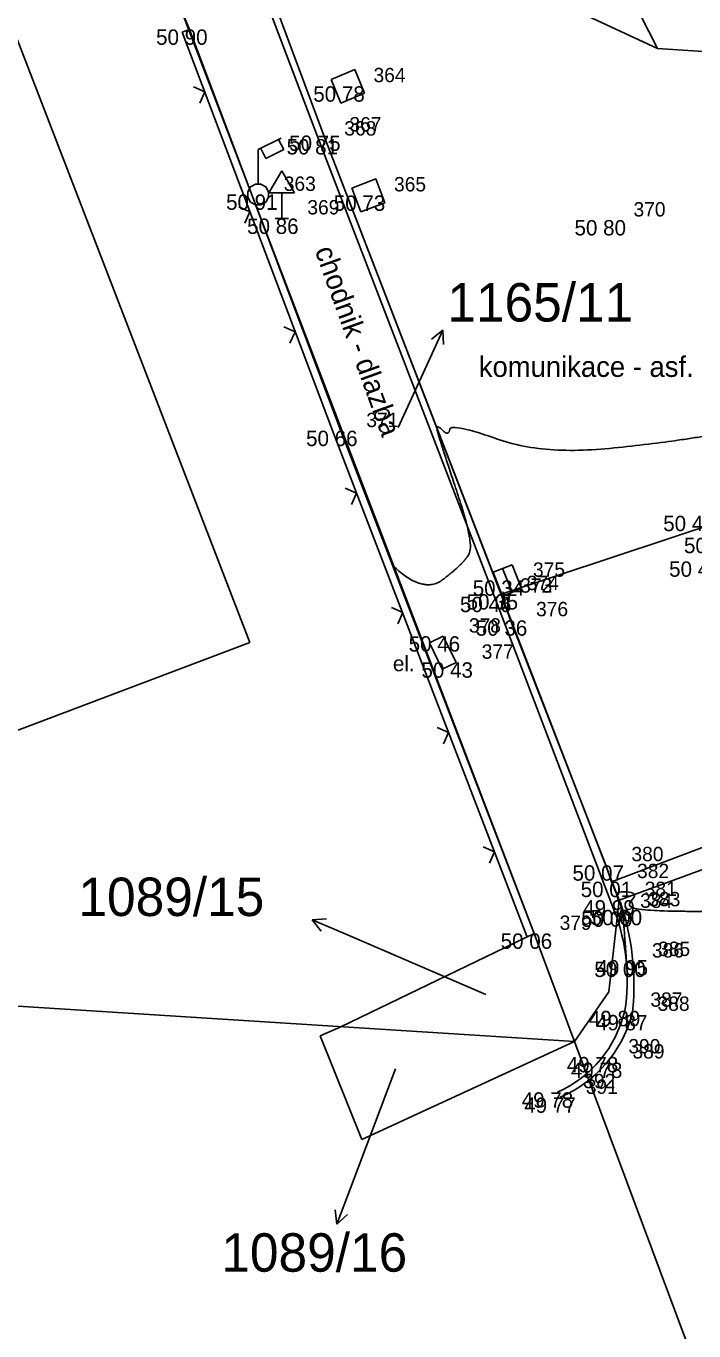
# Model space of a CAD drawing. Extents: x -704057 to -703795, y -1008732 to -1008584.
# Drawn here: x -703998.45 to -703985.42, y -1008681.82 to -1008656.35 of the extents above; entities that cross this region are included whole.
import ezdxf

# ---------------------------------------------------------------- set-up
doc = ezdxf.new("R2010")
doc.units = 0
for name, color, linetype in [('Z_body', 7, 'Continuous'), ('Z_body_cisla', 7, 'Continuous'), ('Z_body_vysky', 7, 'Continuous'), ('Z_dopravni_znaceni', 7, 'Continuous'), ('Z_katastr_cisla_pozemkove', 7, 'Continuous'), ('Z_katastr_hranice', 7, 'Continuous'), ('Z_komunikace_zpevn_pl', 7, 'Continuous'), ('Z_obruby', 7, 'Continuous'), ('Z_oploceni', 7, 'Continuous'), ('Z_popis', 7, 'Continuous'), ('Z_rozhrani_zpevn', 7, 'Continuous'), ('Z_site_pilire', 7, 'Continuous'), ('Z_site_znaky_kanalizace', 7, 'Continuous'), ('Z_site_znaky_VO', 7, 'Continuous'), ('Z_site_znaky_vodovod', 7, 'Continuous'), ('Z_vrstevnice_hlavni', 7, 'Continuous'), ('Z_vrstevnice_vedlejsi', 7, 'Continuous'), ('Z_vstupy', 7, 'Continuous')]:
    doc.layers.add(name, color=color, linetype=linetype)

# ---------------------------------------------------------------- blocks, each defined once
blk = doc.blocks.new('POINT_DISPLAY')
blk.add_line((0, 0), (0, 0))
blk = doc.blocks.new('Z212')
for p, q in [((-0.17, 0.17), (0, 0)), ((0, 0), (0.17, 0.17))]:
    blk.add_line(p, q)
blk = doc.blocks.new('Z13')
for p, q in [((0, 0.88), (0.45, 1.1)), ((0.4, 1.07), (0.5, 0.88)), ((0, 0.2), (0, 0.88)), ((0.15, 0.7), (0.05, 0.9)), ((0.5, 0.88), (0.15, 0.7)), ((-0.2, 0.05), (-0.15, 0.15)), ((-0.2, -0.05), (-0.2, 0.05)), ((-0.15, 0.15), (-0.05, 0.2)), ((-0.05, 0.2), (0.05, 0.2)), ((0.05, 0.2), (0.15, 0.15)), ((0.15, 0.15), (0.2, 0.05)), ((0.2, 0.05), (0.2, -0.05)), ((-0.15, -0.15), (-0.2, -0.05)), ((-0.05, -0.2), (-0.15, -0.15)), ((0.05, -0.2), (-0.05, -0.2)), ((0.15, -0.15), (0.05, -0.2)), ((0.2, -0.05), (0.15, -0.15))]:
    blk.add_line(p, q)
blk = doc.blocks.new('Z38')
for p, q in [((0.25, 0.2), (-0.25, 0.2)), ((-0.25, 0.2), (-0.25, -0.2)), ((-0.25, 0), (0.25, 0)), ((0.25, -0.2), (0.25, 0.2)), ((-0.25, -0.2), (0.25, -0.2))]:
    blk.add_line(p, q)
blk = doc.blocks.new('Z608')
for p, q in [((0.25, 0.25), (-0.25, 0.25)), ((-0.25, 0.25), (-0.25, -0.25)), ((0.25, -0.25), (0.25, 0.25)), ((-0.25, -0.25), (0.25, -0.25))]:
    blk.add_line(p, q)
blk = doc.blocks.new('Z527')
for p, q in [((0, 0.93), (-0.25, 0.5)), ((0.25, 0.5), (0, 0.93)), ((-0.25, 0.5), (0.25, 0.5)), ((0, 0), (0, 0.5)), ((-0.13, 0), (0.13, 0))]:
    blk.add_line(p, q)
blk = doc.blocks.new('Z61')
for p, q in [((0, 0.75), (-0.13, 0.5)), ((0, 0), (0, 0.75)), ((0, 0.75), (0.13, 0.5))]:
    blk.add_line(p, q)

msp = doc.modelspace()

# ---------------------------------------------------------------- linework, layer by layer
at = {"layer": 'Z_katastr_cisla_pozemkove'}
for points in [[(-703991.19, -1008664.19), (-703990.63, -1008662.97)], [(-703989.48, -1008675.25), (-703992.18, -1008674.09)], [(-703991.24, -1008676.7), (-703992.12, -1008679.03)]]:
    msp.add_lwpolyline(points, dxfattribs=at)
at = {"layer": 'Z_katastr_hranice'}
for p, q in [((-703986.13, -1008656.79), (-703989.65, -1008649.86)), ((-703986.13, -1008656.79), (-703996.49, -1008651.97)), ((-703992.64, -1008658.49), (-703994.45, -1008653.63)), ((-703996.14, -1008654.16), (-703988.54, -1008674.06)), ((-703994.08, -1008668.38), (-703999.05, -1008655.49)), ((-703977.9, -1008657.35), (-703986.13, -1008656.79)), ((-703986.88, -1008673.41), (-703992.64, -1008658.49)), ((-703994.08, -1008668.38), (-704002.01, -1008671.38)), ((-703987.08, -1008675.2), (-703986.88, -1008673.41)), ((-703987.75, -1008676.17), (-704026.16, -1008673.72)), ((-703988.54, -1008674.06), (-703992.31, -1008675.88)), ((-703982, -1008691.57), (-703988.54, -1008674.06)), ((-703987.75, -1008676.17), (-703987.08, -1008675.2)), ((-703992.31, -1008675.88), (-703992.71, -1008676.06)), ((-703992.71, -1008676.06), (-703991.9, -1008678.08)), ((-703991.9, -1008678.08), (-703987.75, -1008676.17))]:
    msp.add_line(p, q, dxfattribs=at)
at = {"layer": 'Z_komunikace_zpevn_pl'}
for p, q in [((-703994.45, -1008653.63), (-703992.64, -1008658.49)), ((-703992.64, -1008658.49), (-703989.18, -1008667.44)), ((-703989.18, -1008667.44), (-703989, -1008667.95)), ((-703989, -1008667.95), (-703987.14, -1008672.73)), ((-703987.14, -1008672.73), (-703987.03, -1008673.05)), ((-703987.03, -1008673.05), (-703986.88, -1008673.41)), ((-703986.88, -1008673.41), (-703986.81, -1008673.6))]:
    msp.add_line(p, q, dxfattribs=at)
for centre, radius, start, end in [((-703991.75, -1008675.07), 5.158, 353.5102, 16.5257), ((-703989.02, -1008674.98), 2.483, 293.5439, 344.438)]:
    msp.add_arc(centre, radius, start, end, dxfattribs=at)
at = {"layer": 'Z_obruby'}
for p, q in [((-703992.74, -1008658.56), (-703994.6, -1008653.67)), ((-703992.74, -1008658.56), (-703989.31, -1008667.49)), ((-703989.31, -1008667.49), (-703986.97, -1008673.63))]:
    msp.add_line(p, q, dxfattribs=at)
for centre, radius, start, end in [((-703990.49, -1008674.97), 3.768, 350.8881, 20.8839), ((-703989.03, -1008675.04), 2.32, 294.152, 346.8779)]:
    msp.add_arc(centre, radius, start, end, dxfattribs=at)
at = {"layer": 'Z_oploceni'}
for p, q in [((-703995.4, -1008656.47), (-703995.26, -1008656.42)), ((-703995.26, -1008656.42), (-703992.31, -1008664.25)), ((-703995.4, -1008656.47), (-703992.45, -1008664.3)), ((-703992.45, -1008664.3), (-703988.68, -1008674.11)), ((-703992.31, -1008664.25), (-703988.54, -1008674.06))]:
    msp.add_line(p, q, dxfattribs=at)
at = {"layer": 'Z_rozhrani_zpevn'}
for p, q in [((-703989.18, -1008667.44), (-703981.87, -1008665.01)), ((-703987.03, -1008673.05), (-703979.93, -1008670.37)), ((-703986.88, -1008673.41), (-703983.37, -1008672.12))]:
    msp.add_line(p, q, dxfattribs=at)
at = {"layer": 'Z_site_pilire'}
for p, q in [((-703990.58, -1008668.39), (-703990.31, -1008668.26)), ((-703990.33, -1008668.9), (-703990.58, -1008668.39)), ((-703990.06, -1008668.77), (-703990.31, -1008668.26)), ((-703990.33, -1008668.9), (-703990.06, -1008668.77))]:
    msp.add_line(p, q, dxfattribs=at)
at = {"layer": 'Z_vrstevnice_hlavni'}
msp.add_open_spline([(-703986.743, -1008674.608), (-703986.74, -1008674.61), (-703986.737, -1008674.589), (-703986.81, -1008673.6), (-703986.889, -1008673.432), (-703986.955, -1008673.23), (-703986.49, -1008673.267), (-703986.81, -1008673.6), (-703985.37, -1008673.634), (-703985.333, -1008673.63), (-703981.787, -1008673.594), (-703980.2, -1008672.735), (-703978.988, -1008673.004), (-703978.692, -1008673.627), (-703978.153, -1008674.88), (-703977.349, -1008675.544), (-703975.53, -1008676.91)], degree=2, dxfattribs=at)
at = {"layer": 'Z_vrstevnice_vedlejsi'}
msp.add_open_spline([(-703991.305, -1008666.866), (-703990.71, -1008667.458), (-703989.91, -1008666.842), (-703989.702, -1008666.469), (-703990.341, -1008664.544), (-703990.478, -1008664.084), (-703990.202, -1008664.369), (-703990.172, -1008664.089), (-703988.378, -1008664.725), (-703985.803, -1008664.468), (-703984.247, -1008664.174), (-703982.363, -1008663.613), (-703981.838, -1008664.665), (-703981.808, -1008664.722), (-703981.703, -1008664.79), (-703979.237, -1008666.262), (-703979.164, -1008666.207), (-703978.967, -1008666.455), (-703978.04, -1008666.762), (-703976.651, -1008665.634)], degree=2, dxfattribs=at)
at = {"layer": 'Z_vstupy'}
msp.add_line((-703995.66, -1008655.45), (-703995.26, -1008656.42), dxfattribs=at)

# ---------------------------------------------------------------- block references
at = {"layer": 'Z_body'}
for p in [(-703995.26, -1008656.42), (-703992.17, -1008657.53), (-703992.74, -1008658.56), (-703992.64, -1008658.49), (-703993.92, -1008659.64), (-703991.77, -1008659.66), (-703993.46, -1008660.11), (-703987.1, -1008660.14), (-703992.31, -1008664.25), (-703989.06, -1008667.17), (-703989.31, -1008667.49), (-703989.31, -1008667.49), (-703989.18, -1008667.44), (-703989, -1008667.95), (-703990.31, -1008668.26), (-703990.06, -1008668.77), (-703987.14, -1008672.73), (-703987.03, -1008673.05), (-703986.88, -1008673.41), (-703986.97, -1008673.63), (-703986.81, -1008673.6), (-703988.54, -1008674.06), (-703986.74, -1008674.61), (-703986.62, -1008674.58), (-703986.77, -1008675.57), (-703986.63, -1008675.65), (-703987.2, -1008676.47), (-703987.12, -1008676.58), (-703988.08, -1008677.16), (-703988.03, -1008677.26)]:
    msp.add_blockref('POINT_DISPLAY', p, dxfattribs=at)
at = {"layer": 'Z_dopravni_znaceni'}
msp.add_blockref('Z527', (-703993.46, -1008660.11), dxfattribs=at)
at = {"layer": 'Z_katastr_cisla_pozemkove'}
for p, rotation in [((-703990.63, -1008662.97), -24.775100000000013), ((-703992.18, -1008674.09), 66.8014), ((-703992.12, -1008679.03), 159.1932)]:
    msp.add_blockref('Z61', p, dxfattribs=dict(at, rotation=rotation))
at = {"layer": 'Z_oploceni'}
for p, rotation in [((-703994.96, -1008657.64), 110.60000000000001), ((-703994.08, -1008659.98), 110.60000000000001), ((-703993.2, -1008662.32), 110.60000000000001), ((-703992, -1008665.47), 111), ((-703991.1, -1008667.8), 111), ((-703990.21, -1008670.14), 111), ((-703989.31, -1008672.47), 111)]:
    msp.add_blockref('Z212', p, dxfattribs=dict(at, rotation=rotation))
at = {"layer": 'Z_site_znaky_kanalizace', "rotation": -68.39999999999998}
msp.add_blockref('Z38', (-703989.06, -1008667.17), dxfattribs=at)
at = {"layer": 'Z_site_znaky_VO'}
msp.add_blockref('Z13', (-703993.92, -1008659.64), dxfattribs=at)
at = {"layer": 'Z_site_znaky_vodovod'}
for p, rotation in [((-703992.17, -1008657.53), 22.500000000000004), ((-703991.77, -1008659.66), 20.7)]:
    msp.add_blockref('Z608', p, dxfattribs=dict(at, rotation=rotation))

# ---------------------------------------------------------------- texts
at = {"layer": 'Z_body_cisla'}
for s, p in [('364', (-703991.67, -1008657.45)), ('368', (-703992.24, -1008658.49)), ('367', (-703992.14, -1008658.41)), ('363', (-703993.42, -1008659.57)), ('365', (-703991.27, -1008659.58)), ('369', (-703992.96, -1008660.03)), ('370', (-703986.6, -1008660.07)), ('371', (-703991.81, -1008664.18)), ('375', (-703988.56, -1008667.1)), ('372', (-703988.81, -1008667.41)), ('373', (-703988.81, -1008667.41)), ('374', (-703988.68, -1008667.36)), ('376', (-703988.5, -1008667.87)), ('378', (-703989.81, -1008668.19)), ('377', (-703989.56, -1008668.7)), ('380', (-703986.64, -1008672.65)), ('382', (-703986.53, -1008672.98)), ('381', (-703986.38, -1008673.33)), ('384', (-703986.47, -1008673.56)), ('383', (-703986.31, -1008673.53)), ('379', (-703988.04, -1008673.99)), ('386', (-703986.24, -1008674.53)), ('385', (-703986.12, -1008674.5)), ('387', (-703986.27, -1008675.49)), ('388', (-703986.13, -1008675.57)), ('390', (-703986.7, -1008676.4)), ('389', (-703986.62, -1008676.5)), ('392', (-703987.58, -1008677.08)), ('391', (-703987.53, -1008677.19))]:
    msp.add_text(s, height=0.28, dxfattribs=at).set_placement(p)
at = {"layer": 'Z_body_vysky'}
for s, p in [('50 90', (-703995.91, -1008656.72)), ('50 78', (-703992.845, -1008657.83)), ('50 81', (-703993.365, -1008658.86)), ('50 75', (-703993.315, -1008658.79)), ('50 91', (-703994.545, -1008659.94)), ('50 73', (-703992.445, -1008659.96)), ('50 86', (-703994.135, -1008660.41)), ('50 80', (-703987.75, -1008660.44)), ('50 66', (-703992.985, -1008664.55)), ('50 40', (-703986.02, -1008666.21)), ('50 44', (-703985.615, -1008666.64)), ('50 47', (-703985.905, -1008667.1)), ('50 34', (-703989.735, -1008667.47)), ('50 46', (-703989.985, -1008667.79)), ('50 44', (-703989.985, -1008667.79)), ('50 35', (-703989.855, -1008667.74)), ('50 36', (-703989.675, -1008668.25)), ('50 46', (-703990.985, -1008668.56)), ('50 43', (-703990.735, -1008669.07)), ('50 07', (-703987.79, -1008673.03)), ('50 01', (-703987.63, -1008673.35)), ('49 99', (-703987.58, -1008673.71)), ('50 09', (-703987.62, -1008673.93)), ('50 00', (-703987.435, -1008673.9)), ('50 06', (-703989.19, -1008674.36)), ('50 00', (-703987.365, -1008674.91)), ('49 95', (-703987.32, -1008674.88)), ('49 89', (-703987.47, -1008675.87)), ('49 87', (-703987.33, -1008675.95)), ('49 78', (-703987.9, -1008676.77)), ('49 78', (-703987.82, -1008676.88)), ('49 78', (-703988.78, -1008677.46)), ('49 77', (-703988.73, -1008677.56))]:
    msp.add_text(s, height=0.3, dxfattribs=at).set_placement(p)
at = {"layer": 'Z_katastr_cisla_pozemkove'}
for s, p in [('1165/11', (-703990.23, -1008662.12)), ('1089/15', (-703997.425, -1008673.72)), ('1089/16', (-703994.638, -1008680.66))]:
    msp.add_text(s, height=0.75, dxfattribs=at).set_placement(p)
at = {"layer": 'Z_popis'}
msp.add_text('chodnik - dlazba', height=0.4, rotation=289.8, dxfattribs=at).set_placement((-703992.82, -1008660.73))
for s, height, p in [('komunikace - asf.', 0.4, (-703989.617, -1008663.2)), ('el.', 0.3, (-703991.292, -1008668.943))]:
    msp.add_text(s, height=height, dxfattribs=at).set_placement(p)

doc.saveas('drawing.dxf')
